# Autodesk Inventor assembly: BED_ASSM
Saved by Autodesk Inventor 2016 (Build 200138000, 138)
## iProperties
Created: 2016-01
Part Number: BED_ASSM
Document SubType Name: Assembly
Designer: John
Author: John
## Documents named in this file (6)
- D:\3D Printer Designs\John Ledden Designs\DLP Printer\V2\BED_ASSM.iam
- D:\3D Printer Designs\John Ledden Designs\DLP Printer\V2\BedBracket_LH.ipt
- D:\3D Printer Designs\John Ledden Designs\DLP Printer\V2\BedBracket_RH.ipt
- D:\3D Printer Designs\John Ledden Designs\DLP Printer\V2\BracePlate.ipt
- D:\3D Printer Designs\John Ledden Designs\DLP Printer\V2\Bed.ipt
- D:\3D Printer Designs\John Ledden Designs\DLP Printer\V2\M4_10.ipt
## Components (6 placed, 6 different names)
1. BedBracket_LH_1001
2. BedBracket_RH_1002
3. BracePlate_1003
4. Bed_1004
5. M4_10_1005
6. M4_10_1006
